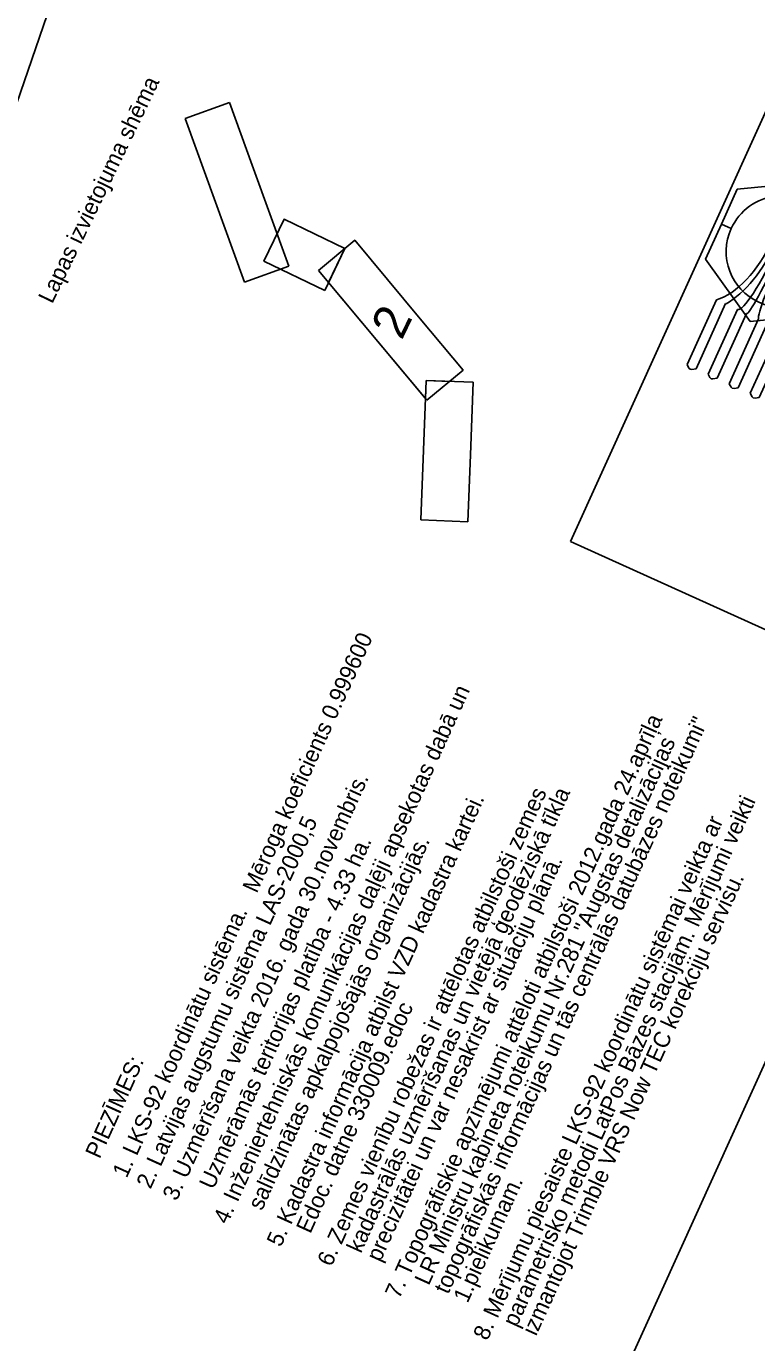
# Model space of a CAD drawing. Extents: x 616607 to 617499, y 408385 to 409695.
# Drawn here: x 617202.2 to 617246.8, y 408964 to 409044.3 of the extents above; entities that cross this region are included whole.
import ezdxf

# ---------------------------------------------------------------- set-up
doc = ezdxf.new("R2010")
doc.units = 0
for name, color, linetype in [('Level 1', 7, 'Continuous'), ('Level 2', 7, 'Continuous'), ('RAMI_PLAN_####_TKST_#', 7, 'Continuous'), ('RAMI_UZMR_####_####_#', 7, 'Continuous'), ('RELJ_NOGA_####_####_#', 7, 'Continuous')]:
    doc.layers.add(name, color=color, linetype=linetype)

# ---------------------------------------------------------------- blocks, each defined once
blk = doc.blocks.new('Logo')
at = {"layer": 'Level 1'}
for p, q in [((-1060.6, 299), (-1077.7, 277)), ((-543.5, 299), (-1060.6, 299)), ((1053.6, 299), (555.4, 299)), ((1070.8, 273.7), (1053.6, 299)), ((-1077.7, 277), (-1081.2, 265.5)), ((-1081.2, 265.5), (-1077.9, 252.7)), ((-1077.9, 252.7), (-1060.6, 227.4)), ((-1060.6, 227.4), (-539.9, 227.4)), ((-539.9, 227.4), (-539.9, 222.8)), ((555.1, 223), (555.1, 227.4)), ((555.1, 227.4), (1053.6, 227.4)), ((1053.6, 227.4), (1070.7, 249.5)), ((1070.7, 249.5), (1074.2, 260.9)), ((1074.2, 260.9), (1070.8, 273.7)), ((-1077.7, 108.5), (-1081.2, 97.1)), ((-1081.2, 97.1), (-1077.9, 84.3)), ((-1060.6, 130.6), (-1077.7, 108.5)), ((-544.2, 130.6), (-1060.6, 130.6)), ((-544.2, 130.5), (-544.2, 130.6)), ((1053.6, 130.6), (543.6, 130.6)), ((543.6, 130.6), (543.6, 130.2)), ((1070.8, 105.3), (1053.6, 130.6)), ((1074.2, 92.4), (1070.8, 105.3)), ((-1077.9, 84.3), (-1060.6, 59)), ((-1060.6, 59), (-544.2, 59)), ((-544.2, 59), (-544.2, 59)), ((539.8, 57.9), (539.8, 59)), ((539.8, 59), (1053.6, 59)), ((1053.6, 59), (1070.7, 81)), ((1070.7, 81), (1074.2, 92.4)), ((-1077.7, -59.9), (-1081.2, -71.3)), ((-1081.2, -71.3), (-1077.9, -84.1)), ((-1077.9, -84.1), (-1060.6, -109.4)), ((-1060.6, -37.9), (-1077.7, -59.9)), ((-542.6, -37.9), (-1060.6, -37.9)), ((-542.6, -36.7), (-542.6, -37.9)), ((541.1, -37.9), (541.1, -37.7)), ((1053.6, -37.9), (541.1, -37.9)), ((1070.8, -63.2), (1053.6, -37.9)), ((1053.6, -109.4), (1070.7, -87.4)), ((1070.7, -87.4), (1074.2, -76)), ((1074.2, -76), (1070.8, -63.2)), ((-1060.6, -109.4), (-542.6, -109.4)), ((-542.6, -109.4), (-542.6, -108.9)), ((544.1, -109.2), (544.1, -109.4)), ((544.1, -109.4), (1053.6, -109.4)), ((-1077.7, -228.3), (-1081.2, -239.7)), ((-1081.2, -239.7), (-1077.9, -252.6)), ((-1077.9, -252.6), (-1060.6, -277.9)), ((-1060.6, -206.3), (-1077.7, -228.3)), ((-547.7, -206.3), (-1060.6, -206.3)), ((-1060.6, -277.9), (-547.1, -277.9)), ((-547.7, -202.5), (-547.7, -206.3)), ((547.1, -206.3), (547.2, -202.4)), ((1053.6, -206.3), (547.1, -206.3)), ((549.8, -277.9), (1053.6, -277.9)), ((1070.8, -231.6), (1053.6, -206.3)), ((1053.6, -277.9), (1070.7, -255.8)), ((1070.7, -255.8), (1074.2, -244.4)), ((1074.2, -244.4), (1070.8, -231.6))]:
    blk.add_line(p, q, dxfattribs=at)
for centre, major_axis, ratio, start_param, end_param in [((3.7, 437.6), (-606.2, 4.2), 0.541463, 0.448589, 2.718476), ((3.7, 413), (-663.8, 4.6), 0.506421, 0.614889, 2.5546), ((0.1, 133.1), (544.3, 1.6), 0.149844, 3.15381, 6.227497), ((-1.5, 59.8), (542.7, 0.8), 0.072629, 3.142706, 6.213096), ((-1.5, -38.9), (542.7, 0.8), 0.071692, 0.008953, 3.063663), ((3.7, -391.9), (-663.8, 4.6), 0.50462, 3.756674, 5.696), ((3.7, -417.6), (-606.2, 4.2), 0.541463, 3.59403, 5.856221), ((0.1, -113.7), (544.3, 1.6), 0.151794, 0.035116, 3.063006)]:
    blk.add_ellipse(centre, major_axis=major_axis, ratio=ratio, start_param=start_param, end_param=end_param, dxfattribs=at)
at = {"layer": 'Level 2'}
for points in [[(-26.1, 416), (-26.1, 493.6), (-305, 493.6), (-583.9, 10.6), (-305, -472.5), (-26.1, -472.5)], [(-26.1, -394.9), (-26.1, -472.5), (252.8, -472.5), (531.7, 10.6), (252.8, 493.6), (-26.1, 493.6), (-26.1, 416)], [(-26.1, -472.5), (-26.1, -394.9)]]:
    blk.add_lwpolyline(points, dxfattribs=at)
for start, end in [(90, 270), (270, 90)]:
    blk.add_arc((-26.1, 10.6), 405.4, start, end, dxfattribs=at)

msp = doc.modelspace()

# ---------------------------------------------------------------- linework, layer by layer
at = {"layer": 'RAMI_PLAN_####_TKST_#'}
for p, q in [((617235.402, 409012.876), (617265.213, 409078.563)), ((617158.243, 408784.967), (617287, 409068.676)), ((617211.917, 409038.652), (617214.614, 409039.628)), ((617214.614, 409039.628), (617216.001, 409035.8)), ((617215.532, 409028.67), (617211.917, 409038.652)), ((617216.001, 409035.8), (617218.229, 409029.646)), ((617220.045, 409029.391), (617222.248, 409031.228)), ((617226.239, 409026.443), (617222.248, 409031.228)), ((617215.532, 409028.67), (617218.229, 409029.646)), ((617220.045, 409029.391), (617226.644, 409021.479)), ((617228.847, 409023.316), (617226.239, 409026.443)), ((617226.644, 409021.479), (617228.847, 409023.316)), ((617226.599, 409022.679), (617226.276, 409014.181)), ((617226.599, 409022.679), (617229.465, 409022.57)), ((617229.297, 409018.141), (617229.465, 409022.57)), ((617229.142, 409014.072), (617229.297, 409018.141)), ((617226.276, 409014.181), (617229.142, 409014.072)), ((617235.402, 409012.876), (617257.189, 409002.989))]:
    msp.add_line(p, q, dxfattribs=at)
msp.add_lwpolyline([(617220.422, 409028.171), (617216.714, 409029.961), (617217.944, 409032.511), (617221.653, 409030.721), (617220.422, 409028.171)], dxfattribs=at)
msp.add_lwpolyline([(617226.599, 409022.679), (617228.019, 409022.625), (617228.847, 409023.316), (617226.239, 409026.443), (617222.248, 409031.228), (617221.645, 409030.725), (617221.653, 409030.721), (617220.657, 409028.657), (617226.558, 409021.583)], close=True, dxfattribs=at)
at = {"layer": 'RAMI_UZMR_####_####_#'}
msp.add_lwpolyline([(617101.571, 408748.246), (617213.472, 409074.039), (617215.883, 409140.56), (617165.121, 409241.478), (617252.137, 409353.424), (617269.572, 409425.099), (617332.631, 409510.312), (617439.945, 409622.037), (617425.373, 409635.959), (617242.079, 409440.82), (617216.614, 409355.716), (617136.613, 409246.751), (617191.828, 409115.62), (617145.545, 408952.8)], dxfattribs=at)
at = {"layer": 'RELJ_NOGA_####_####_#'}
msp.add_open_spline([(617164.214, 408966.743), (617164.067, 408966.559), (617163.746, 408966.808), (617163.516, 408966.861), (617163.258, 408966.92), (617163, 408966.979), (617162.742, 408967.038), (617162.506, 408967.092), (617162.27, 408967.145), (617162.033, 408967.199), (617161.839, 408967.244), (617161.499, 408967.338), (617161.53, 408967.523), (617162.076, 408970.795), (617163.848, 408974.182), (617165.139, 408977.462), (617166.432, 408980.748), (617167.724, 408984.034), (617169.019, 408987.319), (617170.314, 408990.606), (617171.612, 408993.892), (617172.906, 408997.179), (617174.2, 409000.463), (617175.346, 409003.8), (617176.537, 409007.126), (617179.936, 409016.621), (617183.209, 409026.15), (617185.744, 409035.924), (617186.657, 409039.444), (617186.852, 409043.096), (617187.532, 409046.664), (617188.191, 409050.122), (617189.04, 409053.52), (617189.932, 409056.942), (617189.98, 409057.126), (617190.012, 409057.369), (617190.199, 409057.442), (617190.492, 409057.556), (617190.793, 409057.447), (617191.088, 409057.419), (617191.386, 409057.391), (617191.684, 409057.369), (617191.981, 409057.328), (617192.587, 409057.244), (617193.186, 409057.135), (617193.777, 409056.97), (617195.009, 409056.627), (617196.209, 409056.219), (617197.396, 409055.759), (617198.619, 409055.285), (617199.811, 409054.744), (617201.035, 409054.276), (617202.236, 409053.817), (617203.458, 409053.413), (617204.671, 409052.991), (617204.777, 409052.954), (617204.889, 409052.983), (617204.996, 409052.903), (617205.146, 409052.79), (617205.251, 409052.619), (617205.213, 409052.483), (617205.152, 409052.266), (617205.006, 409052.028), (617204.832, 409051.838), (617204.408, 409051.373), (617203.987, 409050.962), (617203.555, 409050.533), (617202.561, 409049.55), (617201.563, 409048.573), (617200.565, 409047.597), (617200.116, 409047.158), (617199.367, 409046.94), (617199.151, 409046.35), (617199.035, 409046.033), (617198.919, 409045.717), (617198.803, 409045.4)], degree=3, dxfattribs=at)

# ---------------------------------------------------------------- block references
at = {"layer": 'Level 2', "xscale": 0.0083759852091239, "yscale": 0.0083759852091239, "rotation": 65.58974746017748}
msp.add_blockref('Logo', (617248.459, 409030.701), dxfattribs=at)

# ---------------------------------------------------------------- texts
at = {"layer": 'RAMI_PLAN_####_TKST_#'}
for s, height, rotation, p in [('Lapas izvietojuma shēma', 1, 64.24104, (617203.804, 409027.31)), ('2', 2.157, 64.24104, (617225.107, 409025.087)), ('Mēroga koeficients 0.999600', 1, 65.58975, (617216.274, 408991.383)), ('4. Inženiertehniskās komunikācijas daļēji apsekotas dabā un ', 1, 65.58975, (617214.489, 408971.201)), ('7. Topogrāfiskie apzīmējumi attēloti atbilstoši 2012.gada 24.aprīļa ', 1, 65.58975, (617224.96, 408966.662)), ('    topogrāfiskās informācijas un tās centrālās datubāzes noteikumi" ', 1, 65.58975, (617227.328, 408965.587)), ('    LR Ministru kabineta noteikumu Nr.281 "Augstas detalizācijas', 1, 65.58975, (617226.144, 408966.124)), ('3. Uzmērīšana veikta 2016. gada 30.novembris.', 1, 65.58975, (617211.393, 408972.628)), ('5. Kadastra informācija atbilst VZD kadastra kartei.', 1, 65.58975, (617217.742, 408969.819)), ('6. Zemes vienību robežas ir attēlotas atbilstoši zemes', 1, 65.58975, (617220.827, 408968.623)), ('    kadastrālās uzmērīšanas un vietējā ģeodēziskā tīkla ', 1, 65.58975, (617222.011, 408968.085)), ('    parametrisko metodi LatPos Bāzes stacijām. Mērījumi veikti ', 1, 65.58975, (617231.509, 408963.58)), ('2. Latvijas augstumu sistēma LAS-2000,5', 1, 65.58975, (617209.798, 408973.359)), ('8. Mērījumu piesaiste LKS-92 koordinātu sistēmai veikta ar ', 1, 65.58975, (617230.331, 408964.115)), ('Uzmērāmās teritorijas platība - 4.33 ha.', 1, 65.58975, (617213.628, 408973.323)), ('salīdzinātas apkalpojošajās organizācijās.', 1, 65.58975, (617216.593, 408972.045)), ('    precizitātei un var nesakrist ar situāciju plānā.', 1, 65.58975, (617223.194, 408967.548)), ('    izmantojot Trimble VRS Now TEC korekciju servisu.', 1, 65.58975, (617232.688, 408963.045)), ('1. LKS-92 koordinātu sistēma. ', 1, 65.58975, (617208.341, 408974.023)), ('    Edoc. datne 330009.edoc', 1, 65.58975, (617218.926, 408969.282)), ('PIEZĪMES:', 1, 65.58975, (617206.69, 408975.197)), ('    1.pielikumam.', 1, 65.58975, (617228.512, 408965.05))]:
    msp.add_text(s, height=height, rotation=rotation, dxfattribs=at).set_placement(p)

doc.saveas('drawing.dxf')
